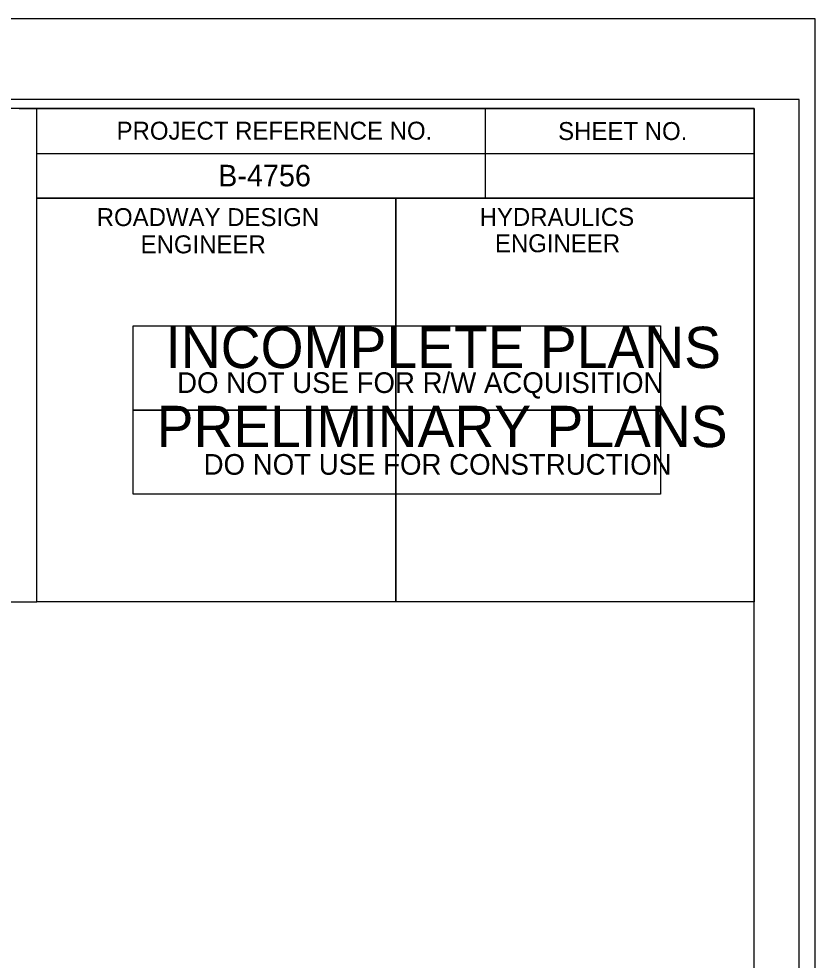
# Model space of a CAD drawing. Extents: x 2431000 to 2534000, y 645879 to 714000.
# Drawn here: x 2469872.8 to 2470094.9, y 672216.1 to 672478.6 of the extents above; entities that cross this region are included whole.
import ezdxf

# ---------------------------------------------------------------- set-up
doc = ezdxf.new("R2010")
doc.units = 0
for name, color, linetype in [('KHA_LOGO', 7, 'Continuous'), ('Sheet DOT Grid CELL', 7, 'Continuous'), ('Sheet Plan CELL', 7, 'Continuous'), ('Sheet Plot Border Inside CELL', 7, 'Continuous'), ('Sheet Plot Border Outside CELL', 7, 'Continuous'), ('Sheet Profile CELL', 7, 'Continuous'), ('Sheet Profile Grid Major CELL', 7, 'Continuous'), ('Sheet Profile Grid Middle CELL', 7, 'Continuous'), ('Sheet Profile Grid Minor CELL', 7, 'Continuous'), ('Sheet Sticker Incomplete CELL', 7, 'Continuous'), ('Sheet Sticker Preliminary CELL', 7, 'Continuous')]:
    doc.layers.add(name, color=color, linetype=linetype)

msp = doc.modelspace()

# ---------------------------------------------------------------- linework, layer by layer
at = {"layer": 'KHA_LOGO'}
msp.add_lwpolyline([(2469777.88, 672316.08), (2469877.88, 672316.08), (2469877.88, 672453.63), (2469777.88, 672453.63)], close=True, dxfattribs=at)
at = {"layer": 'Sheet DOT Grid CELL'}
msp.add_line((2470077.93, 671953.63), (2470077.93, 672316.08), dxfattribs=at)
at = {"layer": 'Sheet Plot Border Inside CELL'}
msp.add_lwpolyline([(2468424.43, 671401.13), (2470090.43, 671401.13), (2470090.43, 672456.13), (2468424.43, 672456.13)], close=True, dxfattribs=at)
at = {"layer": 'Sheet Plot Border Outside CELL'}
msp.add_lwpolyline([(2468411.43, 671378.63), (2470094.93, 671378.63), (2470094.93, 672478.63), (2468411.43, 672478.63)], close=True, dxfattribs=at)
at = {"layer": 'Sheet Profile CELL'}
for p, q in [((2470002.93, 672453.58), (2470002.93, 672428.58)), ((2469877.88, 672441.08), (2470077.93, 672441.08)), ((2469977.93, 672428.58), (2469977.93, 672316.13))]:
    msp.add_line(p, q, dxfattribs=at)
for points in [[(2470077.93, 672453.63), (2468577.93, 672453.63), (2468577.93, 671403.63), (2470077.93, 671403.63)], [(2469877.88, 672453.63), (2470077.93, 672453.63), (2470077.93, 672428.58), (2469877.88, 672428.58)], [(2469877.88, 672428.58), (2469977.93, 672428.58), (2469977.93, 672316.08), (2469877.88, 672316.08)], [(2469977.93, 672428.58), (2470077.93, 672428.58), (2470077.93, 672316.08), (2469977.93, 672316.08)]]:
    msp.add_lwpolyline(points, close=True, dxfattribs=at)
at = {"layer": 'Sheet Profile Grid Major CELL'}
for points in [[(2469877.88, 672403.63), (2469877.93, 672403.63)], [(2469877.93, 672353.63), (2469877.88, 672353.63)]]:
    msp.add_lwpolyline(points, dxfattribs=at)
at = {"layer": 'Sheet Profile Grid Middle CELL'}
msp.add_lwpolyline([(2469877.93, 672378.63), (2469877.88, 672378.63)], dxfattribs=at)
at = {"layer": 'Sheet Profile Grid Minor CELL'}
for p, q in [((2469877.88, 672448.63), (2469877.93, 672448.63)), ((2469877.93, 672443.63), (2469877.88, 672443.63)), ((2469877.88, 672438.63), (2469877.93, 672438.63))]:
    msp.add_line(p, q, dxfattribs=at)
for points in [[(2469872.93, 672453.63), (2469882.93, 672453.63)], [(2469877.93, 672433.63), (2469877.88, 672433.63)], [(2469877.88, 672423.63), (2469877.93, 672423.63)], [(2469877.88, 672413.63), (2469877.93, 672413.63)], [(2469877.93, 672408.63), (2469877.88, 672408.63)], [(2469877.88, 672398.63), (2469877.93, 672398.63)], [(2469877.93, 672393.63), (2469877.88, 672393.63)], [(2469877.88, 672388.63), (2469877.93, 672388.63)], [(2469877.93, 672383.63), (2469877.88, 672383.63)], [(2469877.88, 672373.63), (2469877.93, 672373.63)], [(2469877.93, 672368.63), (2469877.88, 672368.63)], [(2469877.88, 672363.63), (2469877.93, 672363.63)], [(2469877.93, 672358.63), (2469877.88, 672358.63)], [(2469877.88, 672348.63), (2469877.93, 672348.63)], [(2469877.93, 672343.53), (2469877.88, 672343.53)], [(2469877.88, 672338.63), (2469877.93, 672338.63)], [(2469877.93, 672333.63), (2469877.88, 672333.63)], [(2469877.88, 672323.63), (2469877.93, 672323.63)]]:
    msp.add_lwpolyline(points, dxfattribs=at)
at = {"layer": 'Sheet Sticker Incomplete CELL'}
msp.add_lwpolyline([(2469904.76, 672369.54), (2469904.76, 672393.04), (2470051.76, 672393.04), (2470051.76, 672369.54)], close=True, dxfattribs=at)
at = {"layer": 'Sheet Sticker Preliminary CELL'}
msp.add_lwpolyline([(2469904.76, 672346.04), (2469904.76, 672369.54), (2470051.76, 672369.54), (2470051.76, 672346.04)], close=True, dxfattribs=at)

# ---------------------------------------------------------------- texts
at = {"layer": 'Sheet Plan CELL'}
msp.add_text('B-4756', height=6, dxfattribs=at).set_placement((2469928.42, 672431.92))
at = {"layer": 'Sheet Profile CELL'}
for s, height, p in [('PROJECT REFERENCE NO.', 5.0001, (2469900.09, 672444.94)), ('SHEET NO.', 5, (2470023.24, 672444.84)), ('ROADWAY DESIGN', 5.0001, (2469894.54, 672420.84)), ('HYDRAULICS', 5, (2470001.35, 672420.89)), ('ENGINEER', 5, (2469906.79, 672413.24)), ('ENGINEER', 5, (2470005.6, 672413.54))]:
    msp.add_text(s, height=height, dxfattribs=at).set_placement(p)
at = {"layer": 'Sheet Sticker Incomplete CELL'}
for s, height, p in [('INCOMPLETE PLANS', 11.52, (2469913.72, 672381.25)), ('DO NOT USE FOR R/W ACQUISITION', 5.76, (2469916.97, 672374.3))]:
    msp.add_text(s, height=height, dxfattribs=at).set_placement(p)
at = {"layer": 'Sheet Sticker Preliminary CELL'}
for s, height, p in [('PRELIMINARY PLANS', 11.52, (2469911.27, 672359.2)), ('DO NOT USE FOR CONSTRUCTION', 5.76, (2469924.37, 672351.5))]:
    msp.add_text(s, height=height, dxfattribs=at).set_placement(p)

doc.saveas('drawing.dxf')
